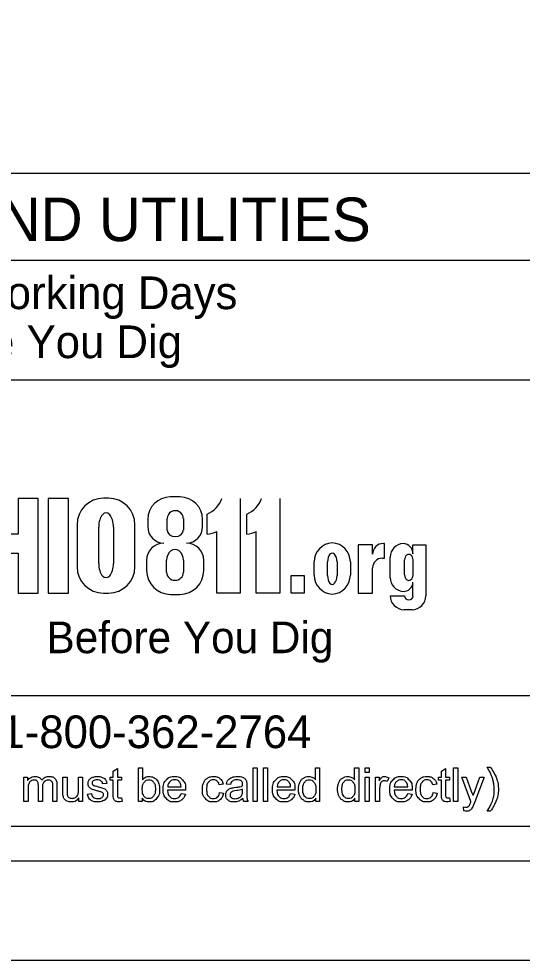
# Model space of a CAD drawing. Extents: x 0 to 34, y 0 to 22.
# Drawn here: x 5.428 to 7.969, y 0 to 4.754 of the extents above; entities that cross this region are included whole.
import ezdxf

# ---------------------------------------------------------------- set-up
doc = ezdxf.new("R2010")
doc.units = 0
for name, color, linetype in [('SH_Border', 7, 'Continuous'), ('SH_Cut_Line', 7, 'Continuous'), ('SH_Data', 7, 'Continuous')]:
    doc.layers.add(name, color=color, linetype=linetype)

msp = doc.modelspace()

# ---------------------------------------------------------------- linework, layer by layer
at = {"layer": 'SH_Border'}
msp.add_lwpolyline([(2, 21.5), (33.5, 21.5), (33.5, 0.5), (2, 0.5)], close=True, dxfattribs=at)
at = {"layer": 'SH_Cut_Line'}
msp.add_lwpolyline([(0, 0), (34, 0), (34, 22), (0, 22)], close=True, dxfattribs=at)
at = {"layer": 'SH_Data'}
for p, q in [((3.224, 3.975), (8.449, 3.975)), ((3.224, 3.535), (8.449, 3.535)), ((3.224, 2.93), (8.449, 2.93)), ((5.8804, 2.3328), (5.8557, 2.3328)), ((6.2416, 2.3393), (6.1927, 2.3393)), ((6.5453, 2.3313), (6.5453, 1.8533)), ((6.7454, 2.3313), (6.7454, 1.8533)), ((6.3786, 2.151), (6.3786, 2.2528)), ((6.5787, 2.151), (6.5787, 2.2528)), ((5.7221, 2.1991), (5.7221, 1.987)), ((5.831, 2.004), (5.831, 2.1867)), ((5.9054, 2.1867), (5.9054, 2.004)), ((6.0141, 1.987), (6.0141, 2.1991)), ((6.0787, 2.2253), (6.0787, 2.189)), ((6.1775, 2.172), (6.1775, 2.2307)), ((6.2584, 2.2307), (6.2584, 2.172)), ((6.3555, 2.189), (6.3555, 2.2253)), ((6.4268, 1.8533), (6.4268, 2.1649)), ((6.6269, 1.8533), (6.6269, 2.1649)), ((7.2141, 2.0967), (7.1411, 2.0967)), ((7.1411, 2.0967), (7.1411, 1.8533)), ((7.2141, 2.0496), (7.2141, 2.0967)), ((7.2748, 2.1045), (7.2689, 2.1045)), ((7.2748, 2.03), (7.2748, 2.1045)), ((7.418, 2.0518), (7.418, 2.0981)), ((7.418, 2.0981), (7.4831, 2.0981)), ((7.4831, 2.0981), (7.4831, 1.8398)), ((6.0731, 2.0189), (6.0731, 1.968)), ((6.1739, 1.9591), (6.1739, 2.0203)), ((6.2589, 2.0203), (6.2589, 1.9591)), ((6.3616, 1.968), (6.3616, 2.0189)), ((6.9192, 1.9442), (6.9192, 2.0119)), ((6.9864, 1.943), (6.9864, 2.0119)), ((7.0345, 2.0119), (7.0345, 1.943)), ((7.1017, 2.0119), (7.1017, 1.9442)), ((7.2634, 2.03), (7.2748, 2.03)), ((7.3031, 1.9316), (7.3031, 2.0356)), ((7.3753, 1.9455), (7.3753, 2.0217)), ((7.418, 2.0217), (7.418, 1.9455)), ((7.2141, 1.8533), (7.2141, 1.9807)), ((7.418, 1.8398), (7.418, 1.9091)), ((5.8557, 1.8533), (5.8804, 1.8533)), ((6.1941, 1.8471), (6.2407, 1.8471)), ((6.5453, 1.8533), (6.4268, 1.8533)), ((6.7454, 1.8533), (6.6269, 1.8533)), ((7.1411, 1.8533), (7.2141, 1.8533)), ((7.3031, 1.8398), (7.3753, 1.8398)), ((7.4133, 1.77), (7.373, 1.77)), ((8.449, 1.3351), (3.224, 1.3351)), ((8.449, 0.675), (3.224, 0.675))]:
    msp.add_line(p, q, dxfattribs=at)
for points in [[(5.3476, 2.0554), (5.4237, 2.0554), (5.4237, 1.8533), (5.5252, 1.8533), (5.5252, 2.3313), (5.4237, 2.3313), (5.4237, 2.151), (5.3476, 2.151), (5.3476, 2.3313)], [(5.576, 1.8533), (5.6787, 1.8533), (5.6787, 2.3313), (5.576, 2.3313), (5.576, 1.8533)], [(6.1596, 2.1054), (6.1596, 2.1053)], [(6.2751, 2.1053), (6.2751, 2.1054)], [(5.9045, 0.8379), (5.9045, 0.9086), (5.8891, 0.9086), (5.8891, 0.9247), (5.9045, 0.9247), (5.9045, 0.9551), (5.9253, 0.9676), (5.9253, 0.9247), (5.946, 0.9247), (5.946, 0.9086), (5.9253, 0.9086), (5.9253, 0.8366)], [(6.0513, 0.8019), (6.032, 0.8019), (6.032, 0.9713), (6.0528, 0.9713), (6.0528, 0.911)], [(6.6105, 0.8019), (6.6105, 0.9713), (6.6313, 0.9713), (6.6313, 0.8019), (6.6105, 0.8019)], [(6.663, 0.8019), (6.663, 0.9713), (6.6838, 0.9713), (6.6838, 0.8019), (6.663, 0.8019)], [(6.9258, 0.9106), (6.9258, 0.9713), (6.9466, 0.9713), (6.9466, 0.8019), (6.9273, 0.8019)], [(7.1231, 0.9106), (7.1231, 0.9713), (7.1439, 0.9713), (7.1439, 0.8019), (7.1246, 0.8019)], [(7.1766, 0.9474), (7.1766, 0.9713), (7.1974, 0.9713), (7.1974, 0.9474), (7.1766, 0.9474)], [(7.5615, 0.8379), (7.5615, 0.9086), (7.5462, 0.9086), (7.5462, 0.9247), (7.5615, 0.9247), (7.5615, 0.9551), (7.5823, 0.9676), (7.5823, 0.9247), (7.6031, 0.9247), (7.6031, 0.9086), (7.5823, 0.9086), (7.5823, 0.8366)], [(7.623, 0.8019), (7.623, 0.9713), (7.6438, 0.9713), (7.6438, 0.8019), (7.623, 0.8019)], [(7.7932, 0.9742), (7.808, 0.9742)], [(5.4536, 0.8019), (5.4536, 0.9247), (5.4722, 0.9247), (5.4722, 0.9074)], [(5.6502, 0.8487), (5.6502, 0.9247), (5.671, 0.9247), (5.671, 0.8567)], [(5.7289, 0.859), (5.7289, 0.9247), (5.7497, 0.9247), (5.7497, 0.8019), (5.7311, 0.8019)], [(7.1766, 0.8019), (7.1766, 0.9247), (7.1974, 0.9247), (7.1974, 0.8019), (7.1766, 0.8019)], [(7.2288, 0.8019), (7.2288, 0.9247), (7.2475, 0.9247), (7.2475, 0.9061)], [(7.2954, 0.9208), (7.2882, 0.9015)], [(7.7108, 0.8018), (7.6642, 0.9247), (7.6866, 0.9247), (7.7121, 0.8538)], [(7.7296, 0.8531), (7.7559, 0.9247), (7.7767, 0.9247), (7.7301, 0.7998)], [(5.4744, 0.8656), (5.4744, 0.8019), (5.4536, 0.8019)], [(5.5473, 0.8732), (5.5473, 0.8019), (5.5265, 0.8019), (5.5265, 0.8816)], [(5.62, 0.8862), (5.62, 0.8019), (5.5992, 0.8019), (5.5992, 0.8792)], [(5.8714, 0.893), (5.851, 0.8902)], [(6.2698, 0.858), (6.1782, 0.858)], [(6.1794, 0.875), (6.2479, 0.875)], [(6.4597, 0.8886), (6.4394, 0.8855)], [(6.4963, 0.8869), (6.4759, 0.8896)], [(6.5577, 0.8559), (6.5578, 0.8635)], [(6.5787, 0.8811), (6.5787, 0.8534)], [(6.8221, 0.858), (6.7306, 0.858)], [(6.7317, 0.875), (6.8003, 0.875)], [(7.2496, 0.8662), (7.2496, 0.8019), (7.2288, 0.8019)], [(7.4138, 0.858), (7.3223, 0.858)], [(7.3235, 0.875), (7.392, 0.875)], [(7.538, 0.8886), (7.5178, 0.8855)], [(5.7311, 0.8019), (5.7311, 0.8201)], [(5.7739, 0.8386), (5.7945, 0.8418)], [(5.946, 0.8205), (5.949, 0.8021)], [(6.0513, 0.8173), (6.0513, 0.8019)], [(6.2477, 0.8416), (6.2692, 0.8389)], [(6.4412, 0.8469), (6.4616, 0.8441)], [(6.8, 0.8416), (6.8215, 0.8389)], [(6.9273, 0.8019), (6.9273, 0.8174)], [(7.1246, 0.8019), (7.1246, 0.8174)], [(7.3918, 0.8416), (7.4133, 0.8389)], [(7.5196, 0.8469), (7.54, 0.8441)], [(7.6031, 0.8205), (7.6061, 0.8021)], [(6.5853, 0.8019), (6.5636, 0.8019)], [(7.6752, 0.7548), (7.6728, 0.7743)], [(7.808, 0.7521), (7.7932, 0.7521)]]:
    msp.add_lwpolyline(points, dxfattribs=at)
msp.add_lwpolyline([(6.8034, 1.943), (6.8693, 1.943), (6.8693, 1.8533), (6.8034, 1.8533)], close=True, dxfattribs=at)
for centre, radius, start, end in [((5.8557, 2.1991), 0.1337, 90, 180), ((5.8804, 2.1991), 0.1337, 0, 90), ((6.1927, 2.2253), 0.114, 90, 180), ((6.2416, 2.2253), 0.114, 0, 90), ((6.3279, 2.3749), 0.1322, 292.5572, 340.7355), ((6.528, 2.3749), 0.1322, 292.5572, 340.7355), ((6.1623, 2.189), 0.0837, 180, 268.1442), ((6.2719, 2.189), 0.0837, 272.2058, 0), ((6.3666, 2.2826), 0.1322, 275.1733, 297.0931), ((6.5668, 2.2826), 0.1322, 275.1733, 297.0931), ((6.1596, 2.0189), 0.0865, 90, 180), ((6.2751, 2.0189), 0.0865, 0, 90), ((7.0147, 2.0119), 0.0956, 92.5886, 180), ((7.0061, 2.0119), 0.0956, 0, 87.4114), ((7.2689, 2.0496), 0.0548, 90, 180), ((7.3717, 2.0356), 0.0686, 92.6865, 180), ((7.3657, 2.0518), 0.0524, 0, 86.9262), ((7.2634, 1.9807), 0.0493, 90, 180), ((5.8557, 1.987), 0.1337, 180, 270), ((5.8804, 1.987), 0.1337, 270, 0), ((6.1941, 1.968), 0.1209, 180, 270), ((6.2407, 1.968), 0.1209, 270, 0), ((7.0147, 1.9442), 0.0956, 180, 267.4114), ((7.0061, 1.9442), 0.0956, 272.5886, 0), ((7.3723, 1.9316), 0.0692, 180, 265.7132), ((7.3713, 1.9091), 0.0467, 264.7825, 0), ((7.373, 1.8398), 0.0699, 180, 270), ((7.4133, 1.8398), 0.0699, 270, 0)]:
    msp.add_arc(centre, radius, start, end, dxfattribs=at)
for centre, major_axis, ratio, start_param, end_param in [((5.8682, 2.1867), (0, 0.0723), 0.514403, 4.712389, 7.853982), ((6.2179, 2.2307), (0.0404, 0), 0.969373, 0, 3.141593), ((6.2179, 2.172), (0.0404, 0), 0.818453, 3.141593, 6.283185), ((6.2164, 2.0203), (0, 0.0535), 0.794529, 4.712389, 7.853982), ((7.0104, 2.0119), (0, 0.0434), 0.553236, 4.712389, 7.853982), ((7.3967, 2.0217), (0, 0.0275), 0.777179, 4.712389, 7.853982), ((5.8682, 2.004), (0, 0.0723), 0.514403, 1.570796, 4.712389), ((6.2164, 1.9591), (0.0425, 0), 0.959837, 3.141593, 6.283185), ((7.0104, 1.943), (0, 0.046), 0.522014, 1.570796, 4.712389), ((7.3967, 1.9455), (0, 0.0275), 0.777179, 1.570796, 4.712389), ((7.3967, 1.8398), (0.0214, 0), 0.959012, 3.141593, 6.283185)]:
    msp.add_ellipse(centre, major_axis=major_axis, ratio=ratio, start_param=start_param, end_param=end_param, dxfattribs=at)
for points, degree in [([(7.7932, 0.7521), (7.8276, 0.8075), (7.8276, 0.8631), (7.8276, 0.8848), (7.8227, 0.9062), (7.8188, 0.9236), (7.8117, 0.9395), (7.8072, 0.9499), (7.7932, 0.9742)], 3), ([(7.808, 0.9742), (7.8298, 0.9452), (7.8402, 0.9159), (7.8491, 0.8907), (7.8491, 0.8632), (7.8491, 0.832), (7.8371, 0.8029), (7.8251, 0.7738), (7.808, 0.7521)], 3), ([(5.4722, 0.9074), (5.4779, 0.9164), (5.4875, 0.9219), (5.4971, 0.9274), (5.5094, 0.9274), (5.523, 0.9274), (5.5318, 0.9218), (5.5405, 0.9161), (5.5441, 0.9059), (5.5587, 0.9274), (5.582, 0.9274), (5.6003, 0.9274), (5.6102, 0.9173), (5.62, 0.9072), (5.62, 0.8862)], 3), ([(5.5265, 0.8816), (5.5265, 0.8955), (5.5214, 0.9024), (5.5163, 0.9094), (5.5048, 0.9094), (5.496, 0.9094), (5.4885, 0.9047), (5.4811, 0.9001), (5.4777, 0.8912), (5.4744, 0.8823), (5.4744, 0.8656)], 3), ([(5.5992, 0.8792), (5.5992, 0.8917), (5.5972, 0.8972), (5.5952, 0.9027), (5.5899, 0.906), (5.5845, 0.9094), (5.5774, 0.9094), (5.5644, 0.9094), (5.5559, 0.9007), (5.5473, 0.8921), (5.5473, 0.8732)], 3), ([(5.851, 0.8902), (5.8496, 0.8997), (5.843, 0.9051), (5.8363, 0.9104), (5.8242, 0.9104), (5.8098, 0.9104), (5.8037, 0.9056), (5.7976, 0.9009), (5.7976, 0.8945), (5.7976, 0.8905), (5.8001, 0.8872), (5.8026, 0.8839), (5.8081, 0.8817), (5.8112, 0.8805), (5.8265, 0.8763), (5.8486, 0.8705), (5.8573, 0.8667), (5.8661, 0.863), (5.8711, 0.8558), (5.8761, 0.8486), (5.8761, 0.838), (5.8761, 0.8276), (5.87, 0.8184), (5.8639, 0.8093), (5.8524, 0.8042), (5.841, 0.7992), (5.8265, 0.7992), (5.8025, 0.7992), (5.79, 0.8091), (5.7774, 0.8191), (5.7739, 0.8386)], 3), ([(5.7945, 0.8418), (5.7962, 0.8294), (5.8041, 0.8229), (5.8121, 0.8163), (5.8263, 0.8163), (5.8407, 0.8163), (5.8477, 0.8221), (5.8546, 0.8279), (5.8546, 0.8358), (5.8546, 0.8429), (5.8485, 0.8469), (5.8442, 0.8497), (5.8272, 0.854), (5.8043, 0.8598), (5.7954, 0.864), (5.7866, 0.8682), (5.782, 0.8756), (5.7774, 0.8831), (5.7774, 0.8921), (5.7774, 0.9003), (5.7812, 0.9073), (5.7849, 0.9143), (5.7914, 0.9189), (5.7963, 0.9225), (5.8047, 0.9249), (5.8131, 0.9274), (5.8227, 0.9274), (5.8372, 0.9274), (5.8481, 0.9233), (5.859, 0.9191), (5.8642, 0.912), (5.8694, 0.9049), (5.8714, 0.893)], 3), ([(6.051, 0.8642), (6.051, 0.8422), (6.057, 0.8323), (6.0668, 0.8163), (6.0835, 0.8163), (6.0972, 0.8163), (6.1071, 0.8281), (6.117, 0.84), (6.117, 0.8634), (6.117, 0.8875), (6.1075, 0.8989), (6.098, 0.9104), (6.0845, 0.9104), (6.0709, 0.9104), (6.0609, 0.8985), (6.051, 0.8867), (6.051, 0.8642)], 3), ([(6.0528, 0.911), (6.066, 0.9274), (6.0864, 0.9274), (6.0978, 0.9274), (6.1079, 0.9229), (6.118, 0.9183), (6.1245, 0.91), (6.131, 0.9018), (6.1347, 0.8901), (6.1384, 0.8785), (6.1384, 0.8652), (6.1384, 0.8336), (6.1228, 0.8164), (6.1072, 0.7992), (6.0854, 0.7992), (6.0636, 0.7992), (6.0513, 0.8173)], 3), ([(6.2692, 0.8389), (6.2641, 0.82), (6.2503, 0.8096), (6.2366, 0.7992), (6.2152, 0.7992), (6.1883, 0.7992), (6.1725, 0.8158), (6.1568, 0.8324), (6.1568, 0.8623), (6.1568, 0.8932), (6.1727, 0.9103), (6.1886, 0.9274), (6.2141, 0.9274), (6.2387, 0.9274), (6.2543, 0.9107), (6.2699, 0.8939), (6.2699, 0.8635), (6.2699, 0.8617), (6.2698, 0.858)], 3), ([(6.2479, 0.875), (6.2465, 0.8905), (6.2401, 0.8983), (6.2301, 0.9104), (6.2143, 0.9104), (6.1999, 0.9104), (6.1902, 0.9008), (6.1804, 0.8911), (6.1794, 0.875)], 3), ([(6.4616, 0.8441), (6.4583, 0.8231), (6.4444, 0.8111), (6.4306, 0.7992), (6.4105, 0.7992), (6.3853, 0.7992), (6.37, 0.8157), (6.3547, 0.8321), (6.3547, 0.8629), (6.3547, 0.8827), (6.3613, 0.8976), (6.3679, 0.9125), (6.3813, 0.92), (6.3948, 0.9274), (6.4106, 0.9274), (6.4306, 0.9274), (6.4434, 0.9173), (6.4561, 0.9072), (6.4597, 0.8886)], 3), ([(6.4394, 0.8855), (6.4365, 0.8979), (6.4292, 0.9041), (6.4218, 0.9104), (6.4115, 0.9104), (6.3958, 0.9104), (6.3859, 0.8991), (6.3761, 0.8878), (6.3761, 0.8634), (6.3761, 0.8387), (6.3856, 0.8275), (6.3951, 0.8163), (6.4103, 0.8163), (6.4226, 0.8163), (6.4308, 0.8238), (6.439, 0.8313), (6.4412, 0.8469)], 3), ([(6.5595, 0.817), (6.5479, 0.8073), (6.5372, 0.8032), (6.5265, 0.7992), (6.5143, 0.7992), (6.494, 0.7992), (6.4832, 0.8091), (6.4723, 0.819), (6.4723, 0.8343), (6.4723, 0.8433), (6.4764, 0.8508), (6.4805, 0.8582), (6.4872, 0.8627), (6.4938, 0.8672), (6.5021, 0.8695), (6.5082, 0.8711), (6.5206, 0.8726), (6.5458, 0.8756), (6.5577, 0.8798), (6.5578, 0.8841), (6.5578, 0.8852), (6.5578, 0.898), (6.5519, 0.9032), (6.544, 0.9103), (6.5283, 0.9103), (6.5136, 0.9103), (6.5067, 0.9051), (6.4997, 0.9), (6.4963, 0.8869)], 3), ([(6.4759, 0.8896), (6.4787, 0.9027), (6.4851, 0.9107), (6.4914, 0.9187), (6.5034, 0.9231), (6.5154, 0.9274), (6.5312, 0.9274), (6.547, 0.9274), (6.5568, 0.9237), (6.5666, 0.92), (6.5712, 0.9144), (6.5758, 0.9088), (6.5777, 0.9003), (6.5787, 0.8949), (6.5787, 0.8811)], 3), ([(6.8215, 0.8389), (6.8164, 0.82), (6.8027, 0.8096), (6.7889, 0.7992), (6.7676, 0.7992), (6.7407, 0.7992), (6.7249, 0.8158), (6.7091, 0.8324), (6.7091, 0.8623), (6.7091, 0.8932), (6.7251, 0.9103), (6.741, 0.9274), (6.7664, 0.9274), (6.791, 0.9274), (6.8066, 0.9107), (6.8222, 0.8939), (6.8222, 0.8635), (6.8222, 0.8617), (6.8221, 0.858)], 3), ([(6.8003, 0.875), (6.7989, 0.8905), (6.7924, 0.8983), (6.7825, 0.9104), (6.7666, 0.9104), (6.7523, 0.9104), (6.7425, 0.9008), (6.7328, 0.8911), (6.7317, 0.875)], 3), ([(6.9273, 0.8174), (6.9156, 0.7992), (6.893, 0.7992), (6.8783, 0.7992), (6.866, 0.8073), (6.8537, 0.8154), (6.8469, 0.8299), (6.8402, 0.8444), (6.8402, 0.8632), (6.8402, 0.8816), (6.8463, 0.8965), (6.8524, 0.9115), (6.8646, 0.9195), (6.8769, 0.9274), (6.892, 0.9274), (6.903, 0.9274), (6.9117, 0.9228), (6.9204, 0.9181), (6.9258, 0.9106)], 3), ([(6.8616, 0.8632), (6.8616, 0.8396), (6.8715, 0.8279), (6.8815, 0.8163), (6.895, 0.8163), (6.9086, 0.8163), (6.9182, 0.8274), (6.9277, 0.8386), (6.9277, 0.8615), (6.9277, 0.8867), (6.918, 0.8985), (6.9083, 0.9103), (6.8941, 0.9103), (6.8802, 0.9103), (6.8709, 0.8989), (6.8616, 0.8876), (6.8616, 0.8632)], 3), ([(7.1246, 0.8174), (7.1129, 0.7992), (7.0903, 0.7992), (7.0756, 0.7992), (7.0633, 0.8073), (7.051, 0.8154), (7.0442, 0.8299), (7.0375, 0.8444), (7.0375, 0.8632), (7.0375, 0.8816), (7.0436, 0.8965), (7.0497, 0.9115), (7.0619, 0.9195), (7.0741, 0.9274), (7.0893, 0.9274), (7.1003, 0.9274), (7.109, 0.9228), (7.1176, 0.9181), (7.1231, 0.9106)], 3), ([(7.0589, 0.8632), (7.0589, 0.8396), (7.0688, 0.8279), (7.0788, 0.8163), (7.0923, 0.8163), (7.1059, 0.8163), (7.1155, 0.8274), (7.125, 0.8386), (7.125, 0.8615), (7.125, 0.8867), (7.1153, 0.8985), (7.1056, 0.9103), (7.0914, 0.9103), (7.0775, 0.9103), (7.0682, 0.8989), (7.0589, 0.8876), (7.0589, 0.8632)], 3), ([(7.2475, 0.9061), (7.2547, 0.9191), (7.2607, 0.9233), (7.2668, 0.9274), (7.2741, 0.9274), (7.2846, 0.9274), (7.2954, 0.9208)], 3), ([(7.2882, 0.9015), (7.2806, 0.906), (7.273, 0.906), (7.2662, 0.906), (7.2608, 0.9019), (7.2554, 0.8978), (7.2531, 0.8905), (7.2496, 0.8794), (7.2496, 0.8662)], 3), ([(7.4133, 0.8389), (7.4082, 0.82), (7.3944, 0.8096), (7.3807, 0.7992), (7.3593, 0.7992), (7.3324, 0.7992), (7.3166, 0.8158), (7.3009, 0.8324), (7.3009, 0.8623), (7.3009, 0.8932), (7.3168, 0.9103), (7.3327, 0.9274), (7.3582, 0.9274), (7.3828, 0.9274), (7.3984, 0.9107), (7.414, 0.8939), (7.414, 0.8635), (7.414, 0.8617), (7.4138, 0.858)], 3), ([(7.392, 0.875), (7.3906, 0.8905), (7.3841, 0.8983), (7.3742, 0.9104), (7.3584, 0.9104), (7.344, 0.9104), (7.3343, 0.9008), (7.3245, 0.8911), (7.3235, 0.875)], 3), ([(7.54, 0.8441), (7.5366, 0.8231), (7.5228, 0.8111), (7.509, 0.7992), (7.4889, 0.7992), (7.4637, 0.7992), (7.4484, 0.8157), (7.4331, 0.8321), (7.4331, 0.8629), (7.4331, 0.8827), (7.4397, 0.8976), (7.4463, 0.9125), (7.4597, 0.92), (7.4732, 0.9274), (7.489, 0.9274), (7.509, 0.9274), (7.5217, 0.9173), (7.5345, 0.9072), (7.538, 0.8886)], 3), ([(7.5178, 0.8855), (7.5149, 0.8979), (7.5076, 0.9041), (7.5002, 0.9104), (7.4898, 0.9104), (7.4741, 0.9104), (7.4643, 0.8991), (7.4545, 0.8878), (7.4545, 0.8634), (7.4545, 0.8387), (7.464, 0.8275), (7.4735, 0.8163), (7.4887, 0.8163), (7.501, 0.8163), (7.5092, 0.8238), (7.5174, 0.8313), (7.5196, 0.8469)], 3), ([(5.671, 0.8567), (5.671, 0.8404), (5.6723, 0.8347), (5.6743, 0.8265), (5.6806, 0.8218), (5.687, 0.8172), (5.6963, 0.8172), (5.7057, 0.8172), (5.7139, 0.822), (5.7221, 0.8268), (5.7255, 0.835), (5.7289, 0.8433), (5.7289, 0.859)], 3), ([(6.1782, 0.858), (6.1793, 0.8377), (6.1896, 0.827), (6.1999, 0.8163), (6.2153, 0.8163), (6.2268, 0.8163), (6.2348, 0.8223), (6.2429, 0.8283), (6.2477, 0.8416)], 3), ([(6.5578, 0.8635), (6.5465, 0.8589), (6.5238, 0.8557), (6.511, 0.8538), (6.5056, 0.8515), (6.5003, 0.8492), (6.4974, 0.8448), (6.4945, 0.8403), (6.4945, 0.8349), (6.4945, 0.8266), (6.5008, 0.821), (6.5071, 0.8155), (6.5192, 0.8155), (6.5312, 0.8155), (6.5406, 0.8207), (6.5499, 0.826), (6.5543, 0.8351), (6.5577, 0.8422), (6.5577, 0.8559)], 3), ([(6.7306, 0.858), (6.7317, 0.8377), (6.742, 0.827), (6.7523, 0.8163), (6.7677, 0.8163), (6.7791, 0.8163), (6.7872, 0.8223), (6.7953, 0.8283), (6.8, 0.8416)], 3), ([(7.3223, 0.858), (7.3234, 0.8377), (7.3337, 0.827), (7.344, 0.8163), (7.3594, 0.8163), (7.3709, 0.8163), (7.3789, 0.8223), (7.387, 0.8283), (7.3918, 0.8416)], 3), ([(5.7311, 0.8201), (5.7167, 0.7992), (5.6922, 0.7992), (5.6813, 0.7992), (5.6719, 0.8034), (5.6625, 0.8075), (5.6579, 0.8138), (5.6534, 0.8201), (5.6515, 0.8293), (5.6502, 0.8354), (5.6502, 0.8487)], 3), ([(5.949, 0.8021), (5.9402, 0.8002), (5.9333, 0.8002), (5.922, 0.8002), (5.9158, 0.8038), (5.9095, 0.8074), (5.907, 0.8133), (5.9045, 0.8191), (5.9045, 0.8379)], 3), ([(5.9253, 0.8366), (5.9253, 0.8277), (5.9263, 0.8252), (5.9274, 0.8226), (5.9299, 0.8211), (5.9324, 0.8196), (5.937, 0.8196), (5.9404, 0.8196), (5.946, 0.8205)], 3), ([(6.5636, 0.8019), (6.5604, 0.8084), (6.5595, 0.817)], 2), ([(6.5787, 0.8534), (6.5787, 0.8244), (6.58, 0.8167), (6.5814, 0.809), (6.5853, 0.8019)], 3), ([(7.6061, 0.8021), (7.5973, 0.8002), (7.5904, 0.8002), (7.5791, 0.8002), (7.5729, 0.8038), (7.5666, 0.8074), (7.5641, 0.8133), (7.5615, 0.8191), (7.5615, 0.8379)], 3), ([(7.5823, 0.8366), (7.5823, 0.8277), (7.5834, 0.8252), (7.5845, 0.8226), (7.587, 0.8211), (7.5894, 0.8196), (7.594, 0.8196), (7.5975, 0.8196), (7.6031, 0.8205)], 3), ([(7.7121, 0.8538), (7.7171, 0.8404), (7.721, 0.8255), (7.7246, 0.8395), (7.7296, 0.8531)], 3), ([(7.6728, 0.7743), (7.6796, 0.7725), (7.6847, 0.7725), (7.6916, 0.7725), (7.6958, 0.7748), (7.7, 0.7771), (7.7026, 0.7813), (7.7046, 0.7844), (7.709, 0.7967), (7.7095, 0.7985), (7.7108, 0.8018)], 3), ([(7.7301, 0.7998), (7.7226, 0.7796), (7.7184, 0.772), (7.7129, 0.7618), (7.7057, 0.757), (7.6985, 0.7522), (7.6886, 0.7522), (7.6826, 0.7522), (7.6752, 0.7548)], 3)]:
    msp.add_open_spline(points, degree=degree, dxfattribs=at)

# ---------------------------------------------------------------- texts
for s, height, p in [('UNDERGROUND UTILITIES', 0.22, (3.3966, 3.6311)), ('Contact Two Working Days', 0.165, (3.8584, 3.2877)), ('Before You Dig', 0.165, (4.7555, 3.0402)), ('Before You Dig', 0.15972, (5.5674, 1.5503)), ('OHIO811, 8-1-1, or 1-800-362-2764', 0.165, (3.3851, 1.0708))]:
    msp.add_text(s, height=height, dxfattribs=at).set_placement(p)

doc.saveas('drawing.dxf')
